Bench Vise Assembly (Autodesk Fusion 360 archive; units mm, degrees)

design "Bench Vice Assembly" references "Handle Bar", "Nut", "Jaw Plate", "Jaw Screw", "Fixed Jaw", "Sliding Jaw", "Base", "Vice Nut"
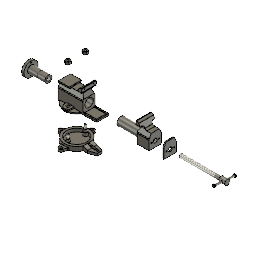
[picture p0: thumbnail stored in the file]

design "Jaw Screw"
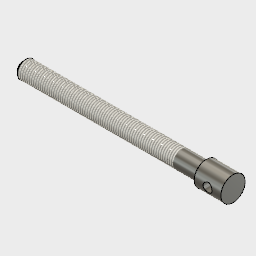
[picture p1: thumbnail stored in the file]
sketch "Sketch1" plane through (0, 0, 0) normal (1, 0, 0) x axis (0, 0, -1)
  circle C1 centre (0, 0) radius 8
  dimension "d1" diameter C1 = 16
extrude "Extrude1" new body sketch "Sketch1" distance 165
sketch "Sketch2" plane through (82.5, 0, 0) normal (1, 0, 0) x axis (0, 0, -1)
  circle C1 centre (0, 0) radius 8
  circle C2 centre (0, 0) radius 11
  dimension "d4" diameter C2 = 22
extrude "Extrude2" add sketch "Sketch2" along normal blind 24
sketch "Sketch3"
sketch "Sketch4"
  line L1 (82.5, 11) -> (82.5, -11)
  line L2 (123.0204, 0) -> (0, 0)
  line L3 (106.5, 11) -> (106.5, -11)
  circle C1 centre (94.5, 0) radius 4
  point P6 (94.5, 0)
  dimension "d7" diameter C1 = 8
  dimension "d8" distance P6 L3 = 12
extrude "Extrude3" cut sketch "Sketch4" profile of C1 no distance stored
chamfer "Chamfer1" distance 3 rotateAngle 45
thread "Thread1" ThreadOffset 0 ThreadLength 140

design "Jaw Plate"
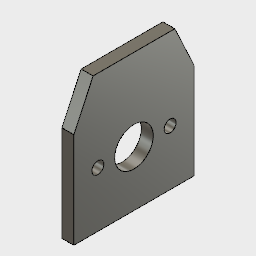
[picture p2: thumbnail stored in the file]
sketch "Sketch1" plane through (0, 0, 0) normal (1, 0, 0) x axis (0, 0, -1)
  line L1 (0, 43.6951) -> (0, 0)
  line L2 (-25, 39.8439) -> (-25, 0)
  line L3 (-17, 57) -> (-25, 39.8439)
  line L4 (17, 57) -> (-17, 57)
  line L5 (25, 39.8439) -> (17, 57)
  line L6 (25, 0) -> (25, 39.8439)
  line L7 (-25, 0) -> (25, 0)
  point P4 (-25, 0)
  point P9 (25, 0)
  point P6 (-17, 57)
  point P7 (17, 57)
  dimension "d1" distance P4 P9 = 50
  dimension "d2" distance P6 P7 = 34
  dimension "d3" distance L4 L7 = 57
  dimension "d4" angle L2 L3 = 25
extrude "Extrude1" new body sketch "Sketch1" profile of L2 L3 L4 L5 L6 L7 along normal blind 5
sketch "Sketch2" plane through (5, 0, 0) normal (1, 0, 0) x axis (0, 0, -1)
  line L1 (25, 39.8439) -> (25, 0)
  line L2 (17, 57) -> (25, 39.8439)
  line L3 (-17, 57) -> (17, 57)
  line L4 (-25, 39.8439) -> (-17, 57)
  line L5 (-25, 0) -> (-25, 39.8439)
  line L6 (25, 0) -> (-25, 0)
  line L7 (0, 50.8818) -> (0, 0)
  circle C1 centre (0, 23) radius 8
  circle C2 centre (0, 23) radius 15
  circle C3 centre (-15, 23) radius 2.5
  circle C4 centre (15, 23) radius 2.5
  point P1 (0, 0)
  point P10 (0, 23)
  dimension "d7" distance P1 P10 = 23
  dimension "d8" diameter C1 = 16
  dimension "d9" diameter C2 = 30
  dimension "d10" diameter C3 = 5
extrude "Extrude2" cut sketch "Sketch2" profile of C1 C3 C4 no distance stored

design "Fixed Jaw"
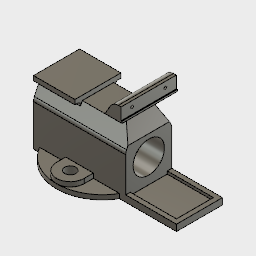
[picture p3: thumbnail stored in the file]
sketch "Sketch1" plane through (0, 0, 0) normal (0, 1, 0) x axis (1, 0, 0)
  circle C1 centre (0, 0) radius 50
  dimension "d1" diameter C1 = 100
extrude "Extrude1" new body sketch "Sketch1" along normal blind 5
sketch "Sketch2" plane through (0, 5, 0) normal (0, 1, 0) x axis (-1, 0, 0)
  line L1 (-15, -35) -> (-15, 35)
  line L2 (15, 35) -> (15, -35)
  line L3 (0, -35) -> (0, 35)
  circle C1 centre (0, 0) radius 50
  arc A1 centre (0, -35) radius 15 clockwise from (15, -35) to (-15, -35)
  arc A2 centre (0, 35) radius 15 clockwise from (-15, 35) to (15, 35)
  point P7 (0, 35)
  point P8 (0, -35)
  dimension "d4" radius A1 = 15
  dimension "d5" distance P7 P8 = 70
extrude "Extrude2" add sketch "Sketch2" profile of L1 A1 L2 A2 along normal blind 5
sketch "Sketch3" plane through (0, 10, 0) normal (0, 1, 0) x axis (-1, 0, 0)
  line L1 (-15, -35) -> (-15, 35)
  line L2 (15, 35) -> (15, -35)
  arc A1 centre (0, 35) radius 15 clockwise from (-15, 35) to (15, 35)
  arc A2 centre (0, -35) radius 15 clockwise from (15, -35) to (-15, -35)
  circle C1 centre (0, 35) radius 6
  circle C2 centre (0, -35) radius 6
  dimension "d8" diameter C2 = 12
extrude "Extrude3" cut sketch "Sketch3" profile of C1 C2 no distance stored
sketch "Sketch4" plane through (0, 0, 0) normal (1, 0, 0) x axis (0, 0, -1)
  line L1 (-50, 5) -> (50, 5)
  line L2 (0, 55.8239) -> (0, 0)
  line L3 (-50, 0) -> (50, 0)
  line L4 (-25, 46.8439) -> (-25, 0)
  line L5 (-17, 64) -> (-25, 46.8439)
  line L6 (17, 64) -> (-17, 64)
  line L7 (25, 46.8439) -> (17, 64)
  line L8 (25, 0) -> (25, 46.8439)
  line L9 (25, 0) -> (-25, 0)
  point P10 (-17, 64)
  point P11 (17, 64)
  dimension "d10" distance L4 L8 = 50
  dimension "d11" distance L6 L9 = 64
  dimension "d12" distance P10 P11 = 34
  dimension "d13" angle L4 L5 = 25
extrude "Extrude4" add sketch "Sketch4" profile of L1 L3 L4 L5 L6 L7 L8 L9 distance 100
fillet "Fillet1" radius 10
sketch "Sketch5" plane through (-50, 0, 0) normal (-1, 0, 0) x axis (0, 0, 1)
  line L1 (-25, 0) -> (-25, 44.627)
  line L2 (25, 0) -> (-25, 0)
  line L3 (25, 44.627) -> (25, 0)
  line L4 (17, 64) -> (24.0631, 48.8532)
  line L5 (-17, 64) -> (17, 64)
  line L6 (-24.0631, 48.8532) -> (-17, 64)
  line L7 (0, 78.169) -> (0, 0)
  line L8 (25, 69) -> (-25, 69)
  line L9 (25, 64) -> (25, 69)
  line L10 (-25, 64) -> (25, 64)
  line L11 (-25, 69) -> (-25, 64)
  arc A1 centre (-15, 44.627) radius 10 clockwise from (-25, 44.627) to (-24.0631, 48.8532)
  arc A2 centre (15, 44.627) radius 10 clockwise from (24.0631, 48.8532) to (25, 44.627)
  point P14 (-25, 69)
  point P15 (25, 69)
  point P17 (-25, 64)
  dimension "d17" distance P14 P15 = 50
  dimension "d18" distance P14 P17 = 5
extrude "Extrude5" add sketch "Sketch5" profile of L5 L8 L9 L10 L11 against normal blind 45
fillet "Fillet2" radius 3
sketch "Sketch6" plane through (50, 0, 0) normal (1, 0, 0) x axis (0, 0, -1)
  line L1 (17, 64) -> (24.0631, 48.8532)
  line L2 (-17, 64) -> (17, 64)
  line L3 (-24.0631, 48.8532) -> (-17, 64)
  line L4 (-25, 0) -> (-25, 44.627)
  line L5 (25, 0) -> (-25, 0)
  line L6 (25, 44.627) -> (25, 0)
  line L7 (25, 0) -> (-25, 0)
  line L8 (25, 7) -> (25, 0)
  line L9 (-25, 7) -> (25, 7)
  line L10 (-25, 0) -> (-25, 7)
  arc A1 centre (15, 44.627) radius 10 clockwise from (24.0631, 48.8532) to (25, 44.627)
  arc A2 centre (-15, 44.627) radius 10 clockwise from (-25, 44.627) to (-24.0631, 48.8532)
  point P13 (25, 0)
  point P14 (25, 7)
  dimension "d22" distance P13 P14 = 7
extrude "Extrude6" add sketch "Sketch6" profile of L4 L5 L6 L7 L8 L9 L10 along normal blind 55
sketch "Sketch7"
  line L1 (50, 64) -> (-5, 64)
  line L2 (50, 92) -> (50, 64)
  line L3 (47, 92) -> (50, 92)
  line L4 (25.0607, 64) -> (38.3397, 87)
  line L5 (25.0607, 64) -> (50, 64)
  arc A1 centre (47, 82) radius 10 clockwise from (38.3397, 87) to (47, 92)
  point P5 (50, 64)
  point P6 (50, 92)
  point P7 (47, 92)
  dimension "d25" distance P5 P6 = 28
  dimension "d26" distance P6 P7 = 3
  dimension "d27" radius A1 = 10
  dimension "d28" angle L1 L4 = 120
extrude "Extrude7" add sketch "Sketch7" distance 60
sketch "Sketch8" plane through (0, 0, 30) normal (0, 0, 1) x axis (1, 0, 0)
  line L1 (47, 92) -> (50, 92)
  line L2 (25.0607, 64) -> (38.3397, 87)
  line L3 (50, 64) -> (25.0607, 64)
  line L4 (50, 92) -> (50, 64)
  line L5 (44.2265, 77) -> (50, 77)
  line L6 (50, 64) -> (50, 48.8532)
  line L7 (50, 52) -> (39.8964, 69.5)
  line L8 (50, 77) -> (50, 52)
  arc A1 centre (47, 82) radius 10 clockwise from (38.3397, 87) to (47, 92)
  arc A2 centre (44.2265, 72) radius 5 clockwise from (39.8964, 69.5) to (44.2265, 77)
  point P14 (50, 52)
  dimension "d31" distance L1 L5 = 15
  dimension "d32" distance L1 P14 = 40
  dimension "d33" radius A2 = 5
  dimension "d34" angle L7 L8 = 30
extrude "Extrude8" cut sketch "Sketch8" profile of L3 L4 L5 A2 L6 L7 L8 no distance stored
sketch "Sketch9" plane through (50, 0, 0) normal (1, 0, 0) x axis (0, 0, -1)
  line L1 (30, 77) -> (-30, 77)
  line L2 (30, 92) -> (30, 77)
  line L3 (-30, 92) -> (30, 92)
  line L4 (-30, 77) -> (-30, 92)
  line L5 (-21.9258, 77) -> (-30, 77)
  line L6 (-30, 36.1214) -> (-15.5816, 67.0417)
  line L7 (-30, 77) -> (-30, 36.1214)
  line L8 (-30, 69.5) -> (-30, 64)
  line L9 (-17, 64) -> (-22.5957, 52)
  arc A1 centre (-21.9258, 70) radius 7 clockwise from (-21.9258, 77) to (-15.5816, 67.0417)
  dimension "d36" radius A1 = 7
extrude "Extrude9" cut sketch "Sketch9" profile of L1 L5 A1 L6 L7 L8 L9 to an object
mirror "Mirror1"
sketch "Sketch10" plane through (50, 0, 0) normal (1, 0, 0) x axis (0, 0, -1)
  line L1 (30, 77) -> (-30, 77)
  line L2 (30, 92) -> (30, 77)
  line L3 (-30, 92) -> (30, 92)
  line L4 (-30, 77) -> (-30, 92)
  line L5 (30, 77) -> (-30, 77)
  line L6 (30, 79) -> (30, 77)
  line L7 (-30, 79) -> (30, 79)
  line L8 (-30, 77) -> (-30, 79)
  point P7 (30, 77)
  point P8 (30, 79)
  dimension "d40" distance P7 P8 = 2
extrude "Extrude10" add sketch "Sketch10" profile of L1 L2 L4 L5 L6 L7 L8 along normal blind 1
sketch "Sketch11" plane through (50, 0, 0) normal (1, 0, 0) x axis (0, 0, -1)
  line L1 (-22.5957, 52) -> (22.5957, 52)
  line L2 (-24.0631, 48.8532) -> (-22.5957, 52)
  line L3 (-25, 7) -> (-25, 44.627)
  line L4 (25, 7) -> (-25, 7)
  line L5 (25, 44.627) -> (25, 7)
  line L6 (22.5957, 52) -> (24.0631, 48.8532)
  line L7 (0, 42.1185) -> (0, 0)
  arc A1 centre (-15, 44.627) radius 10 clockwise from (-25, 44.627) to (-24.0631, 48.8532)
  arc A2 centre (15, 44.627) radius 10 clockwise from (24.0631, 48.8532) to (25, 44.627)
  circle C1 centre (0, 30) radius 17
  point P1 (0, 0)
  point P14 (0, 30)
  dimension "d43" diameter C1 = 34
  dimension "d44" distance P1 P14 = 30
extrude "Extrude11" cut sketch "Sketch11" profile of C1 no distance stored
sketch "Sketch12" plane through (50, 0, 0) normal (1, 0, 0) x axis (0, 0, -1)
  line L1 (30, 79) -> (-30, 79)
  line L2 (30, 92) -> (30, 79)
  line L3 (-30, 92) -> (30, 92)
  line L4 (-30, 79) -> (-30, 92)
  line L5 (-30, 87) -> (30, 87)
  line L6 (0, 104.4277) -> (0, 0)
  circle C1 centre (-18, 86) radius 1.5
  circle C2 centre (18, 86) radius 1.5
  point P6 (-18, 86)
  point P9 (18, 86)
  dimension "d46" diameter C1 = 3
  dimension "d47" distance P6 P9 = 36
  dimension "d48" distance L3 P6 = 6
extrude "Extrude12" cut sketch "Sketch12" profile of C1 L5 C2 against normal blind 5
sketch "Sketch13" plane through (0, 7, 0) normal (0, 1, 0) x axis (-1, 0, 0)
  line L1 (-50, 25) -> (-50, -25)
  line L2 (-105, 25) -> (-50, 25)
  line L3 (-105, -25) -> (-105, 25)
  line L4 (-50, -25) -> (-105, -25)
  line L5 (-100, 20) -> (-50, 20)
  line L6 (-100, -20) -> (-100, 20)
  line L7 (-50, -20) -> (-100, -20)
  dimension "d51" = 5
extrude "Extrude13" cut sketch "Sketch13" profile of L1 L5 L6 L7 against normal blind 3
fillet "Fillet3" radius 10
sketch "Sketch14" plane through (-50, 0, 0) normal (-1, 0, 0) x axis (0, 0, 1)
  line L1 (-25, 0) -> (-25, 44.627)
  line L2 (25, 0) -> (-25, 0)
  line L3 (25, 44.627) -> (25, 0)
  line L4 (18.9901, 59.7321) -> (24.0631, 48.8532)
  line L5 (25, 64) -> (21.7091, 64)
  line L6 (25, 69) -> (25, 64)
  line L7 (-25, 69) -> (25, 69)
  line L8 (-25, 64) -> (-25, 69)
  line L9 (-21.7091, 64) -> (-25, 64)
  line L10 (-24.0631, 48.8532) -> (-18.9901, 59.7321)
  line L11 (0, 61.9125) -> (0, 0)
  circle C1 centre (0, 30) radius 17
  arc A1 centre (-15, 44.627) radius 10 clockwise from (-25, 44.627) to (-24.0631, 48.8532)
  arc A2 centre (15, 44.627) radius 10 clockwise from (24.0631, 48.8532) to (25, 44.627)
  arc A3 centre (21.7091, 61) radius 3 clockwise from (18.9901, 59.7321) to (21.7091, 64)
  arc A4 centre (-21.7091, 61) radius 3 clockwise from (-21.7091, 64) to (-18.9901, 59.7321)
  circle C2 centre (0, 52.5) radius 2.5
  circle C3 centre (0, 7.5) radius 2.5
  circle C4 centre (0, 30) radius 22.5
  dimension "d55" diameter C2 = 5
  dimension "d56" diameter C4 = 45
extrude "Extrude14" cut sketch "Sketch14" profile of C2 C3 against normal blind 10

design "Handle Bar"
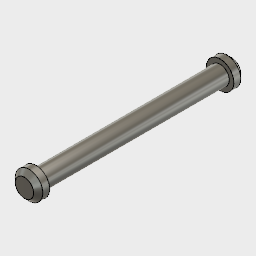
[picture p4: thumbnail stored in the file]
sketch "Sketch1"
  circle C1 centre (0, 0) radius 4
  dimension "d1" diameter C1 = 8
extrude "Extrude1" new body sketch "Sketch1" distance 80
sketch "Sketch2" plane through (0, 0, 40) normal (0, 0, 1) x axis (1, 0, 0)
  circle C1 centre (0, 0) radius 4
  circle C2 centre (0, 0) radius 6
  dimension "d4" diameter C2 = 12
extrude "Extrude2" add sketch "Sketch2" along normal blind 5
chamfer "Chamfer1" distance 2 rotateAngle 45
mirror "Mirror1"

design "Vice Nut"
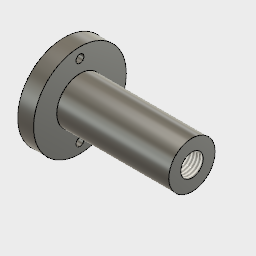
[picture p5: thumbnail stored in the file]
sketch "Sketch1" plane through (0, 0, 0) normal (1, 0, 0) x axis (0, 0, -1)
  circle C1 centre (0, 0) radius 14.5
  dimension "d1" diameter C1 = 29
extrude "Extrude1" new body sketch "Sketch1" along normal blind 70
sketch "Sketch2" plane through (0, 0, 0) normal (-1, 0, 0) x axis (0, 0, 1)
  circle C1 centre (0, 0) radius 14.5
  circle C2 centre (0, 0) radius 29
  dimension "d4" diameter C2 = 58
extrude "Extrude2" add sketch "Sketch2" along normal blind 10
sketch "Sketch3" plane through (-10, 0, 0) normal (-1, 0, 0) x axis (0, 0, 1)
  circle C1 centre (0, 0) radius 29
  circle C2 centre (0, 0) radius 13
  dimension "d7" diameter C2 = 26
extrude "Extrude3" cut sketch "Sketch3" profile of C2 against normal blind 48
sketch "Sketch4" plane through (70, 0, 0) normal (1, 0, 0) x axis (0, 0, -1)
  circle C1 centre (0, 0) radius 14.5
  circle C2 centre (0, 0) radius 8
  dimension "d10" diameter C2 = 16
extrude "Extrude4" cut sketch "Sketch4" profile of C2 no distance stored
chamfer "Chamfer1" distance 4 rotateAngle 45
sketch "Sketch5" plane through (0, 0, 0) normal (1, 0, 0) x axis (0, 0, -1)
  line L1 (0, -34.1673) -> (0, 33.8255)
  circle C1 centre (0, 0) radius 29
  circle C2 centre (0, 0) radius 14.5
  circle C3 centre (0, 0) radius 22.5
  circle C4 centre (0, 22.5) radius 2.5
  circle C5 centre (0, -22.5) radius 2.5
  dimension "d14" diameter C3 = 45
  dimension "d15" diameter C4 = 5
extrude "Extrude5" cut sketch "Sketch5" profile of C4 C5 no distance stored
thread "Thread1"

design "Nut"
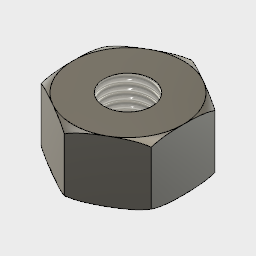
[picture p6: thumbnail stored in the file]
sketch "Sketch1" plane through (0, 0, 0) normal (0, 1, 0) x axis (1, 0, 0)
  line L1 (-9, 5.1962) -> (0, 10.3923)
  line L2 (-9, -5.1962) -> (-9, 5.1962)
  line L3 (0, -10.3923) -> (-9, -5.1962)
  line L4 (9, -5.1962) -> (0, -10.3923)
  line L5 (9, 5.1962) -> (9, -5.1962)
  line L6 (0, 10.3923) -> (9, 5.1962)
  circle C1 centre (0, 0) radius 4.5
  dimension "d1" distance L2 L5 = 18
  dimension "d2" diameter C1 = 9
extrude "Extrude1" new body sketch "Sketch1" distance 10
sketch "Sketch3"
  line L1 (9, 5) -> (9, -5)
  line L2 (12, 5) -> (9, 5)
  line L3 (12, 2) -> (12, 5)
  line L4 (4.5, -5) -> (-4.5, -5)
  line L5 (0, 13.044) -> (0, 0)
  arc A1 centre (8.1021, 1.1021) radius 4 clockwise from (9, 5) to (12, 2)
  point P4 (9, 5)
  point P5 (12, 5)
  dimension "d6" distance P4 P5 = 3
  dimension "d7" radius A1 = 4
revolve "Revolve1" sketch "Sketch3" AlongAngle 360
mirror "Mirror1"
thread "Thread1"

design "Base"
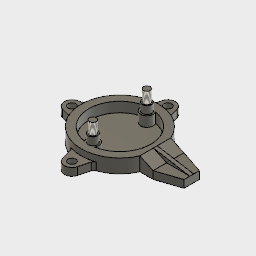
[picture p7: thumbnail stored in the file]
sketch "Sketch1" plane through (0, 0, 0) normal (0, 1, 0) x axis (1, 0, 0)
  circle C1 centre (0, 0) radius 50
  dimension "d1" diameter C1 = 100
extrude "Extrude1" new body sketch "Sketch1" along normal blind 18
sketch "Sketch2" plane through (0, 18, 0) normal (0, 1, 0) x axis (-1, 0, 0)
  circle C1 centre (0, 0) radius 50
  circle C2 centre (0, 0) radius 40
  dimension "d4" diameter C2 = 80
extrude "Extrude2" cut sketch "Sketch2" profile of C2 against normal blind 13
sketch "Sketch3" plane through (0, 18, 0) normal (0, 1, 0) x axis (-1, 0, 0)
  line L1 (-95.7683, 0) -> (0, 0)
  line L2 (-63, -20) -> (-45.8258, -20)
  line L3 (-93, -10) -> (-63, -20)
  line L4 (-93, 10) -> (-93, -10)
  line L5 (-63, 20) -> (-93, 10)
  line L6 (-45.8258, 20) -> (-63, 20)
  circle C1 centre (0, 0) radius 40
  circle C2 centre (0, 0) radius 50
  circle C3 centre (0, 0) radius 50
  point P1 (0, 0)
  point P7 (-93, -10)
  point P8 (-93, 10)
  point P6 (-63, -20)
  dimension "d7" distance P1 L4 = 93
  dimension "d8" distance L2 L6 = 40
  dimension "d9" distance P7 P8 = 20
  dimension "d10" distance P6 P7 = 30
extrude "Extrude3" add sketch "Sketch3" profile of C2 C3 L2 L3 L4 L5 L6 to an object
sketch "Sketch4"
  line L1 (63, 0) -> (63, 18)
  line L2 (63, 10) -> (45.8258, 18)
  line L3 (93, 0) -> (93, 18)
  line L4 (93, 10) -> (63, 10)
  line L5 (93, 18) -> (93, 10)
  line L6 (45.8258, 18) -> (93, 18)
  line L7 (93, 0) -> (63, 0)
  dimension "d13" distance L4 L7 = 10
extrude "Extrude4" cut sketch "Sketch4" profile of L1 L2 L3 L4 L5 L6 no distance stored
sketch "Sketch5"
  line L1 (93, 10) -> (45.8258, 18)
step "Rib" Thickness 5
sketch "Sketch6" plane through (0, 18, 0) normal (0, 1, 0) x axis (-1, 0, 0)
  line L1 (-45.8258, 2.5) -> (-45.8258, 20)
  line L2 (-45.8258, -2.5) -> (-45.8258, 2.5)
  line L3 (-45.8258, -20) -> (-45.8258, -2.5)
  line L4 (-45.8258, 2.5) -> (-93, 2.5)
  line L5 (85.156, 0) -> (0, 0)
  line L6 (0, 59.7587) -> (0, -56.3092)
  arc A1 centre (0, 0) radius 50 clockwise from (-45.8258, 20) to (-45.8258, -20)
  circle C1 centre (0, 0) radius 40
  circle C2 centre (0, -35) radius 8
  circle C3 centre (0, 35) radius 8
  point P1 (0, 0)
  point P13 (0, -35)
  dimension "d17" diameter C2 = 16
  dimension "d18" distance P1 P13 = 35
extrude "Extrude5" add sketch "Sketch6" profile of C1 C2 C3 to an object
sketch "Sketch7" plane through (0, 18, 0) normal (0, 1, 0) x axis (-1, 0, 0)
  line L1 (-45.8258, 2.5) -> (-45.8258, 20)
  line L2 (-45.8258, -2.5) -> (-45.8258, 2.5)
  line L3 (-45.8258, -20) -> (-45.8258, -2.5)
  arc A1 centre (0, 0) radius 50 clockwise from (-45.8258, 20) to (-45.8258, -20)
  circle C1 centre (0, 35) radius 6
  circle C2 centre (0, -35) radius 6
  arc A2 centre (0, 0) radius 40 clockwise from (6.6529, 39.4429) to (6.6529, -39.4429)
  arc A3 centre (0, -35) radius 8 clockwise from (-6.6529, -39.4429) to (6.6529, -39.4429)
  arc A4 centre (0, 0) radius 40 clockwise from (-6.6529, -39.4429) to (-6.6529, 39.4429)
  arc A5 centre (0, 35) radius 8 clockwise from (6.6529, 39.4429) to (-6.6529, 39.4429)
  dimension "d22" diameter C2 = 12
extrude "Extrude6" add sketch "Sketch7" profile of C1 C2 along normal blind 10
sketch "Sketch8" plane through (0, 28, 0) normal (0, 1, 0) x axis (-1, 0, 0)
  circle C1 centre (0, 35) radius 6
  circle C2 centre (0, 35) radius 4.5
  circle C3 centre (0, -35) radius 4.5
  circle C4 centre (0, -35) radius 6
  dimension "d25" diameter C3 = 9
extrude "Extrude7" add sketch "Sketch8" profile of C2 C3 along normal blind 15
thread "Thread1"
thread "Thread2"
sketch "Sketch9" plane through (0, 0, 0) normal (0, -1, 0) x axis (1, 0, 0)
  line L1 (93, 10) -> (93, -10)
  line L2 (63, 20) -> (93, 10)
  line L3 (45.8258, 20) -> (63, 20)
  line L4 (63, -20) -> (45.8258, -20)
  line L5 (93, -10) -> (63, -20)
  line L6 (-54.8103, 0) -> (0, 0)
  line L7 (0, 62.7215) -> (0, 0)
  line L8 (-64.5882, 9.6593) -> (-47.9669, 14.1129)
  line L9 (-47.9669, -14.1129) -> (-64.5882, -9.6593)
  arc A1 centre (0, 0) radius 50 clockwise from (45.8258, -20) to (45.8258, 20)
  arc A2 centre (0, 0) radius 50 clockwise from (45.8258, -20) to (45.8258, 20)
  arc A3 centre (-62, 0) radius 10 clockwise from (-64.5882, -9.6593) to (-64.5882, 9.6593)
  circle C1 centre (-62, 0) radius 5
  point P18 (-62, 0)
  dimension "d28" radius A3 = 10
  dimension "d29" distance L7 P18 = 62
  dimension "d30" angle L8 L9 = 30
  dimension "d31" diameter C1 = 10
extrude "Extrude8" add sketch "Sketch9" profile of A1 A2 L8 A3 L9 C1 against normal blind 10
circular_pattern "C-Pattern1" TotalAngle 360
fillet "Fillet1" radius 5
